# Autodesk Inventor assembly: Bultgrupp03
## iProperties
Created: 2001-12
Part Number: Bultgrupp03
Document SubType Name: Assembly
Designer: Tobben
Control State: 0
Master: False
Checked Out: False
Shininess: 64.0
Length Units: 11269
Angle Units: 11279
Time Units: 11290
Mass Units: 11283
Length Display Precision: 3
Angle Display Precision: 2
Density: 0.0
Volumn: 0.0
Area: 0.0
PropertySet Name: Model Information
Author: Tobben
